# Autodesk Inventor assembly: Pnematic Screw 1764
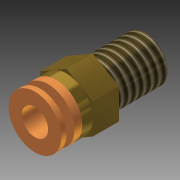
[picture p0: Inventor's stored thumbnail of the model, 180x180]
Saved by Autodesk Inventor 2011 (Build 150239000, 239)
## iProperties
Created: 2010-02
Part Number: Pnematic Screw 1764
Document SubType Name: Assembly
Designer: clee1
Author: clee1
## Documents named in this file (3)
- R:\CAD Archives\Pneumatics\Pnewmatic Screw 1764\Pnematic Screw 1764.iam
- R:\CAD Archives\Pneumatics\Pnewmatic Screw 1764\Pneumatic Screw Part 1 1764.ipt
- R:\CAD Archives\Pneumatics\Pnewmatic Screw 1764\Pneumatic Screw Part 2 1764.ipt
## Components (2 placed, 2 different names)
1. Pneumatic Screw Part 1 1764:1 — Insert:1
2. Pneumatic Screw Part 2 1764:1 — Insert:1
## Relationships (1: Insert 1)
- Insert:1: Pneumatic Screw Part 1 1764:1 ↔ Pneumatic Screw Part 2 1764:1
